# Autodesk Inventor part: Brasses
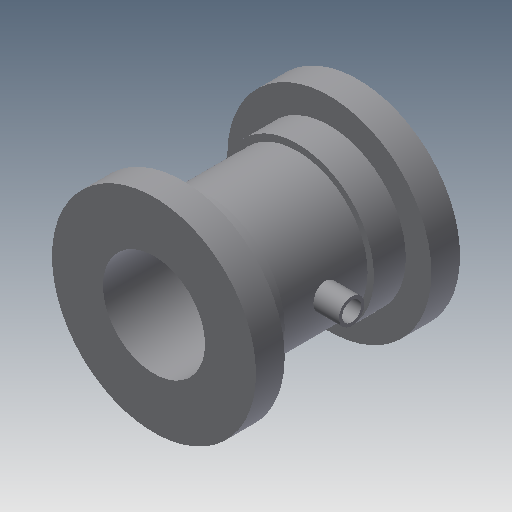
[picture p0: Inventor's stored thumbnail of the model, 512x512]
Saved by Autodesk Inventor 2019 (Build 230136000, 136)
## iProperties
Created: 2009-04
Part Number: Brasses
Document SubType Name: Modeling
Designer: Sham
Density: 1 g/cm^3
Material: Generic
Appearance: Default
Author: Sham
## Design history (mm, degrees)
sketch "Sketch1"
  geometry: L1 (0, 32)-(9, 32); L2 (0, 16)-(64, 16); L3 (64, 32)-(55, 32); L4 (55, 32)-(55, 24); L5 (55, 24)-(47, 24); L6 (19, 22)-(47, 22); L7 (47, 24)-(47, 22); L8 (19, 22)-(19, 24); L9 (19, 24)-(9, 24); L10 (9, 24)-(9, 32); L11 (0, 32)-(0, 16); L12 (64, 32)-(64, 16); L13 (-12.8, 0)-(76.8, 0) reference; 1 further point
  constraints: 24 end point, 7 parallel, 4 perpendicular, 1 collinear, 1 horizontal, 1 vertical alignment, 1 other
  dimensions: "d0" = 9 distance of L1.start L1.end; "d2" = 16 distance from line of L2 point (0, 0); "d3" = 64 distance of L2.start L2.end; "d4" = 24 distance from line of point (0, 0) L5; "d5" = 28 distance of L6.start L6.end; "d6" = 22 distance from line of point (0, 0) L6; "d7" = 8 distance of L4.end L5.end
revolve "Revolution1" sketch "Sketch1" stored, may be unused: angle "d8" = 90 deg
workplane "Work Plane1"
sketch "Sketch2"
  geometry: C1 r 4 at (-32, 0)
  constraints: 1 centre point
  dimensions: "d10" = 8 diameter of C1
extrude "Extrusion1" join sketch "Sketch2" stored distance "d11" = 10; taper "d12" = 0 deg
sketch "Sketch3"
  geometry: C1 r 4 at (0, 0) reference; C2 r 3 at (0, 0)
  constraints: 1 centre point, 1 coincident
  dimensions: "d13" = 6 diameter of C2
extrude "Extrusion2" cut sketch "Sketch3" extent not by distance; stored distance "d14" = 10; taper "d15" = 0 deg
body "Solid1"
